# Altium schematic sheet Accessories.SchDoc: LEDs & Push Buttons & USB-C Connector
size A4; Date: Not used; ApprovedBy: Not used; CheckedBy: Not used; Author: Not used; CompanyName: STMicroelectronics; DrawnBy: Not used; Engineer: Not used; Organization: Not used; Address1: Not used; Address2: Not used; Address3: Not used; Address4: Not used; DocumentNumber: Not used; Revision: Not used; SheetNumber: 4; SheetTotal: 6
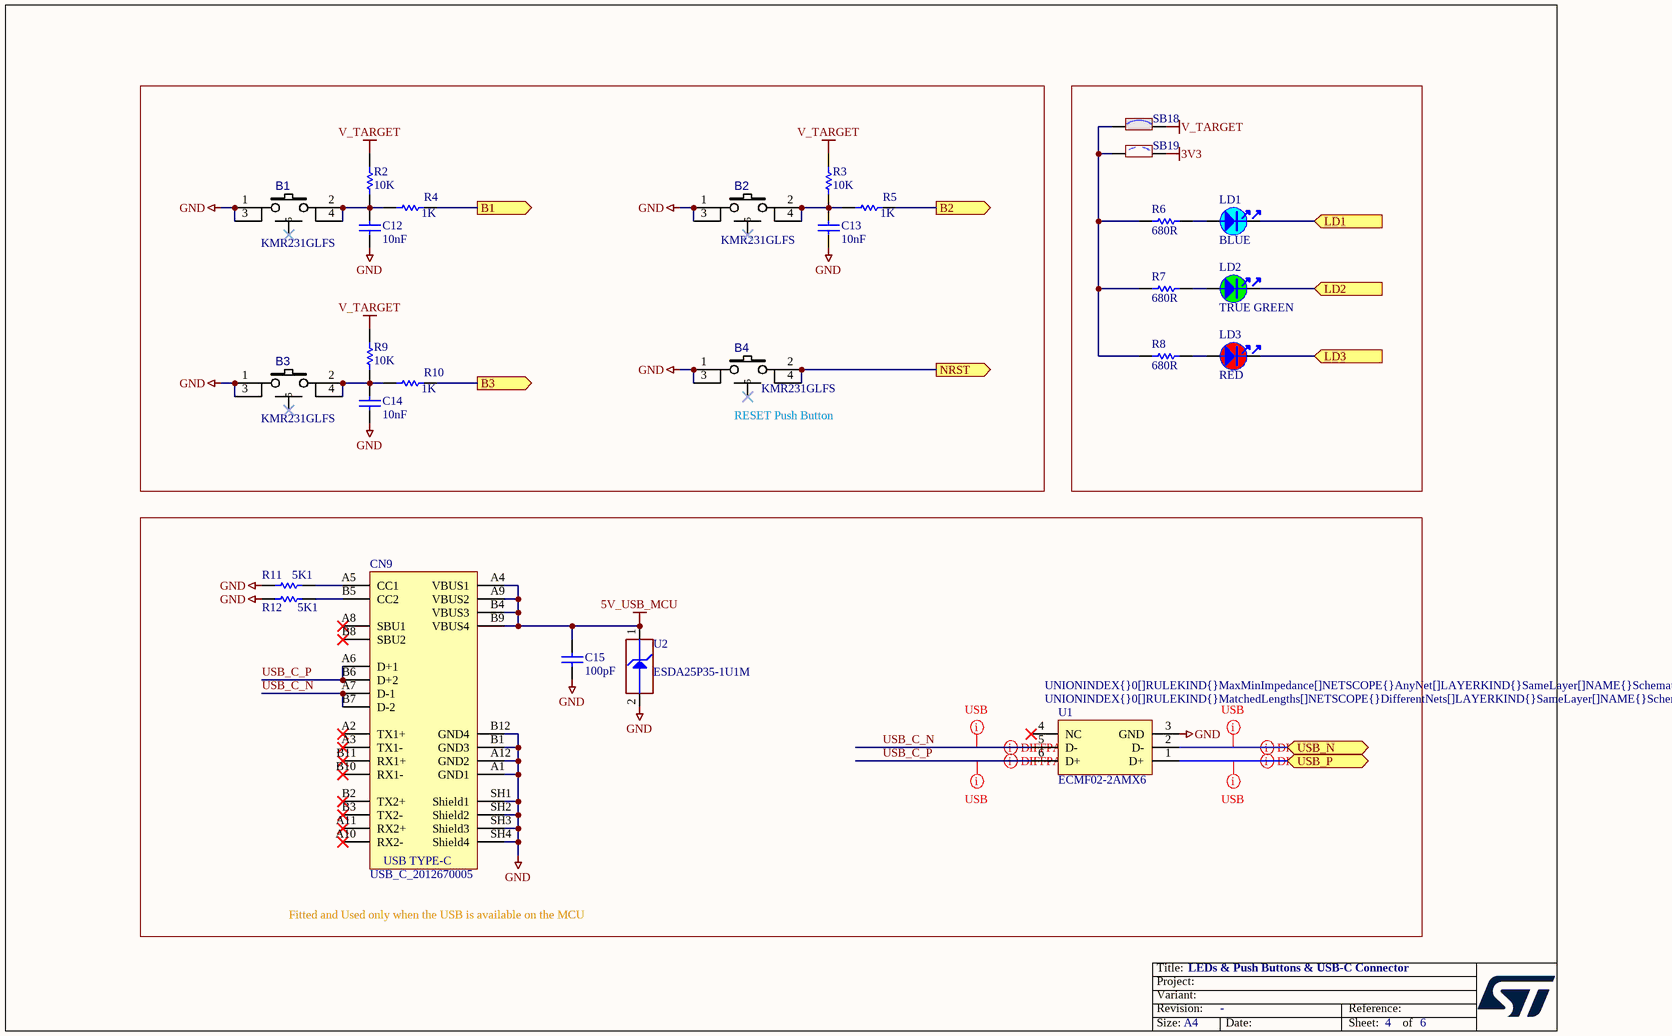
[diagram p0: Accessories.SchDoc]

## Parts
B1  value KMR231GLFS  [SWI_C&K_Y78B23110FP__ITT_KMR231GLFS]  (hidden comment: SW-PUSH-CMS_KMR2_BLACK)
B2  value KMR231GLFS  [SWI_C&K_Y78B23110FP__ITT_KMR231GLFS]  (hidden comment: SW-PUSH-CMS_KMR2_BLACK)
B3  value KMR231GLFS  [SWI_C&K_Y78B23110FP__ITT_KMR231GLFS]  (hidden comment: SW-PUSH-CMS_KMR2_BLACK)
B4  value KMR231GLFS  [SWI_C&K_Y78B23110FP__ITT_KMR231GLFS]  (hidden comment: SW-PUSH-CMS_KMR2_BLACK)
C12  value 10nF  [C0402]  (hidden comment: Capacitor)
C13  value 10nF  [C0402]  (hidden comment: Capacitor)
C14  value 10nF  [C0402]  (hidden comment: Capacitor)
C15  value 100pF  [C0402]  (hidden comment: Capacitor)
CN9  value USB_C_2012670005  [CON_USB-TYPEC_MOLEX_2012670005]  (hidden comment: USB_TYPE_C_Receptacle)
LD1  value BLUE  [LED_0603_VISHAY_VLMB1300-GS08_BLUE_1A2K_H0P8]  (hidden comment: LED_blue)
LD2  value TRUE GREEN  [LED_0603_VISHAY_VLMTG1300-GS08_GREEN_1A2K_H0P8]  (hidden comment: LED_green)
LD3  value RED  [LED_0603_VISHAY_VLMS1300-GS08_RED_1A2K_H0P8]  (hidden comment: LED_red)
R2  value 10K  [R0402]  (hidden comment: Resistor)
R3  value 10K  [R0402]  (hidden comment: Resistor)
R4  value 1K  [R0402]  (hidden comment: Resistor)
R5  value 1K  [R0402]  (hidden comment: Resistor)
R6  value 680R  [R0402]  (hidden comment: Resistor)
R7  value 680R  [R0402]  (hidden comment: Resistor)
R8  value 680R  [R0402]  (hidden comment: Resistor)
R9  value 10K  [R0402]  (hidden comment: Resistor)
R10  value 1K  [R0402]  (hidden comment: Resistor)
R11  value 5K1  [R0402]  (hidden comment: Resistor)
R12  value 5K1  [R0402]  (hidden comment: Resistor)
SB18  SB_ON  [SOLDER-BRIDGE_R0402-0R]  (value not drawn)
SB19  SB_OFF  [SOLDER-BRIDGE_R0402-0R]  (value not drawn)
U1  ECMF02-2AMX6  [ESD_QFN-6L_1P7X1P5_P050]
U2  value ESDA25P35-1U1M  [ESD_QFN1610_2N_1K_2A]  (hidden comment: ESD-TRANSIL)

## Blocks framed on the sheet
RESET Push Button: B1-B4 C12-C14 R2-R5 R9 R10
Fitted and Used only when the USB is available on the MCU: C15 CN9 R11 R12 U1 U2

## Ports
B1 (out), B2 (out), B3 (out), LD1 (in), LD2 (in), LD3 (in), NRST (out), USB_N (bidir), USB_P (bidir)

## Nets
3V3: SB19.2
5V_USB_MCU: C15.2 CN9.A4(VBUS1) CN9.A9(VBUS2) CN9.B4(VBUS3) CN9.B9(VBUS4) U2.1(IO1)
GND: B1.1 B1.3 B2.1 B2.3 B3.1 B3.3 B4.1 B4.3 C12.1 C13.1 C14.1 C15.1 CN9.A1(GND1) CN9.A12(GND2) CN9.B1(GND3) CN9.B12(GND4) CN9.SH1(Shield1) CN9.SH2(Shield2) CN9.SH3(Shield3) CN9.SH4(Shield4) R11.1 R12.1 U1.3(GND) U2.2(GND)
V_TARGET: R2.2 R3.2 R9.2 SB18.2
B1: R4.2 ; port B1
B2: R5.2 ; port B2
B3: R10.2 ; port B3
LD1: LD1.2 ; port LD1
LD2: LD2.2 ; port LD2
LD3: LD3.2 ; port LD3
NRST: B4.2 B4.4 ; port NRST
USB_C_N: CN9.A7(D-1) CN9.B7(D-2) U1.5(D-)
USB_C_P: CN9.A6(D+1) CN9.B6(D+2) U1.6(D+)
USB_N: U1.2(D-) ; port USB_N
USB_P: U1.1(D+) ; port USB_P
NetB1_2: B1.2 B1.4 C12.2 R2.1 R4.1
NetB2_2: B2.2 B2.4 C13.2 R3.1 R5.1
NetB3_2: B3.2 B3.4 C14.2 R9.1 R10.1
NetCN9_A5: CN9.A5(CC1) R11.2
NetCN9_B5: CN9.B5(CC2) R12.2
NetLD1_1: LD1.1 R6.2
NetLD2_1: LD2.1 R7.2
NetLD3_1: LD3.1 R8.2
NetR6_1: R6.1 R7.1 R8.1 SB18.1 SB19.1

Not connected (* = marked no-connect by the designer): B1 5*; B2 5*; B3 5*; B4 5*; CN9 A2(TX1+)* A3(TX1-)* A8(SBU1)* A10(RX2-)* A11(RX2+)* B2(TX2+)* B3(TX2-)* B8(SBU2)* B10(RX1-)* B11(RX1+)*; U1 4(NC)*

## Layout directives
differential pair; rule Impedance Constraint [Min = 85.00    Max = 95.00    ]: USB_C_N, USB_C_P, USB_N, USB_P
rule Undefined; rule Matched Net Lengths [Tolerance = 2mm]; rule Impedance Constraint [Min = 85.00    Max = 95.00    ]: USB_C_N, USB_C_P, USB_N, USB_P

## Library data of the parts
B1-B4 = MCD-01485: Microminiature Tact Switch for SMT - KMR 2 Series - 1.9 mm height; Part_Type: Misc; Manufacturer: C&K; Part_Preference: Recommended; Component_Country_Of_Origin: France
C12-C14 = MCD-02198: Capacitor, MLCC, 10nF, 50V, X7R, +/-10%, 0402, T=0.5mm; Part_Preference: Recommended; Manufacturer: YAGEO; Manufacturer_Part_Number: CC0402KRX7R9BB103; Order_Code_RS: 6169644; Component_Country_Of_Origin: China
C15 = MCD-00205: Capacitor, MLCC, 100pF, 50V, NPO, +/-5%, 0402, T=0.5mm; Manufacturer_Part_Number: CC0402JRNPO9BN101; Manufacturer: YAGEO; Part_Preference: Recommended; Component_Country_Of_Origin: China
CN9 = MCD-02421: USB_TypeC, 24 pins, RA, SMD, T=3.71mm (USB Certified 3.1); Part_Type: Connector; Part_Preference: Recommended; Manufacturer: MOLEX; Manufacturer_Part_Number: 2012670005; Order_Code_RS: 176-8434; Component_Country_Of_Origin: Unknown
LD1 = MCD-00584: LED Blue, 0603 SMD, 3.3 V Forward Voltage; Part_Type: Display; Manufacturer_Part_Number: VLMB1300-GS08; Manufacturer: VISHAY; Part_Preference: Recommended; Order_Code_RS: 7730430; Component_Country_Of_Origin: China
LD2 = MCD-00589: LED Green, 0603 SMD, Fw Voltage = 2.8V - 3.6V; Part_Type: Display; Manufacturer_Part_Number: VLMTG1300-GS08; Manufacturer: VISHAY; Part_Preference: Recommended; Order_Code_RS: 7730452; Component_Country_Of_Origin: China
LD3 = MCD-00587: LED Red, 0603 SMD, 2V Forward Voltage; Part_Type: Display; Manufacturer_Part_Number: VLMS1300-GS08; Manufacturer: VISHAY; Part_Preference: Recommended; Alternate_Internal_Part_Number: MCD-02401; Component_Country_Of_Origin: China
R2 R3 R9 = MCD-00053: Resistor, 10K, 0402, +/-1%, 1/16W; BMS_Part_Number: 9131590; Part_Preference: Recommended; Manufacturer: YAGEO; Manufacturer_Part_Number: RC0402FR-0710KL; Component_Country_Of_Origin: China
R4 R5 R10 = MCD-00061: Resistor, 1K, 0402, +/-1%,1/16W; Manufacturer_Part_Number: RC0402FR-071KL; Manufacturer: YAGEO; Part_Preference: Recommended; Component_Country_Of_Origin: China
R6-R8 = MCD-00507: Resistor, 680R, 0402, +/-1%, 1/16W; Manufacturer_Part_Number: RC0402FR-07680RL; Manufacturer: YAGEO; Part_Preference: Recommended; Component_Country_Of_Origin: China
R11 R12 = MCD-00333: Resistor, 5K1, 0402, +/-1%, 1/16W; Manufacturer_Part_Number: RC0402FR-075K1L; Manufacturer: YAGEO; Part_Preference: Recommended; Component_Country_Of_Origin: China
SB18 = MCD-01618: Solder Bridge 0402 ON; Part_Type: Misc; Part_Preference: Recommended; Manufacturer: YAGEO; Manufacturer_Part_Number: RC0402JR-070RL; Order_Code_RS: 618-5804; Component_Country_Of_Origin: China
SB19 = MCD-02162: Solder Bridge 0402 OFF; Part_Type: Misc; Part_Preference: Recommended; Manufacturer: YAGEO; Manufacturer_Part_Number: RC0402JR-070RL; Order_Code_RS: 618-5804; Component_Country_Of_Origin: China; Value: SB0402
U1 = MCD-00649: Common mode filter with ESD protection for USB 2.0 interface; Part_Type: Diode; Manufacturer: STMICROELECTRONICS; BMS_Part_Number: 9151138; Part_Preference: Recommended; Manufacturer_HQ_COO: EU; Component_Country_Of_Origin: China
U2 = MCD-01207: High power Transient voltage suppressor:25V/35A EOS and ESD transients protection.; Part_Type: Diode; Manufacturer: STMICROELECTRONICS; BMS_Part_Number: 9179045; Part_Preference: Recommended; Manufacturer_HQ_COO: EU; Component_Country_Of_Origin: China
